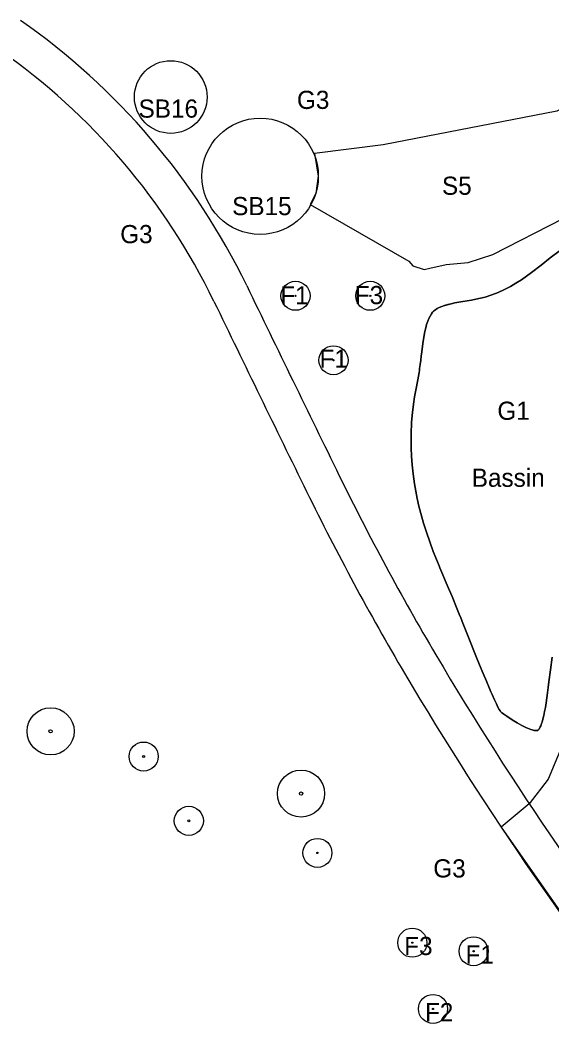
# Model space of a CAD drawing. Extents: x 0 to 512122, y 0 to 6212554.
# Drawn here: x 511664.9 to 511701.5, y 6211598.5 to 6211668.5 of the extents above; entities that cross this region are included whole.
import ezdxf

# ---------------------------------------------------------------- set-up
doc = ezdxf.new("R2010")
doc.units = 0
for name, color, linetype in [('_LØ2', 7, 'Continuous'), ('_ny fruit trees', 7, 'Continuous'), ('_Paths', 7, 'Continuous'), ('_S5_spansk kørvel', 7, 'Continuous'), ('_solitaire tree_ K3', 7, 'Continuous'), ('Bassin - bottom', 7, 'Continuous'), ('TV_U_AFM_Symbl_Gul', 7, 'Continuous'), ('TV_U_LYS_Mastenummer', 7, 'Continuous'), ('TV_U_LYS_Nyx330-Trafiksti-x2', 7, 'Continuous')]:
    doc.layers.add(name, color=color, linetype=linetype)

msp = doc.modelspace()

# ---------------------------------------------------------------- linework, layer by layer
at = {"layer": '_LØ2'}
msp.add_lwpolyline([(511711.121, 6211599.231), (511715.557, 6211615.262), (511713.457, 6211620.03), (511710.963, 6211624.728), (511708.398, 6211628.07), (511706.573, 6211631.603), (511706.496, 6211631.752), (511706.246, 6211631.811), (511705.782, 6211631.027), (511705.291, 6211628.924), (511704.763, 6211625.953), (511704.035, 6211622.995), (511702.625, 6211619.644), (511701.216, 6211616.293), (511699.914, 6211614.606), (511697.985, 6211612.99), (511704.249, 6211604.056), (511710.152, 6211596.395)], close=True, dxfattribs=at)
at = {"layer": '_ny fruit trees'}
msp.add_line((511683.868, 6211637.129), (511683.868, 6211637.129), dxfattribs=at)
for centre, radius in [((511683.843, 6211649.558), 1), ((511688.982, 6211649.558), 1), ((511683.843, 6211649.558), 0.0426), ((511688.982, 6211649.558), 0.0426), ((511686.453, 6211645.121), 1), ((511686.453, 6211645.121), 0.0426), ((511685.348, 6211611.219), 1), ((511685.348, 6211611.219), 0.0426), ((511691.873, 6211605.041), 1), ((511691.873, 6211605.041), 0.0426), ((511696.089, 6211604.454), 1), ((511696.089, 6211604.454), 0.0426), ((511693.299, 6211600.486), 1), ((511693.299, 6211600.486), 0.0426)]:
    msp.add_circle(centre, radius, dxfattribs=at)
at = {"layer": '_Paths'}
for centre, radius, start, end in [((511637.775, 6211629.597), 47.447, 25.82266, 55.10263), ((511637.775, 6211629.597), 44.947, 25.82266, 55.07394), ((514583.875, 6213055.236), 3225.465, 205.82266, 206.081191), ((514583.875, 6213055.236), 3227.965, 205.82266, 206.081191), ((511848.567, 6211716.335), 180.047, 206.08119, 210.53527), ((511848.567, 6211716.335), 182.547, 206.08119, 210.53527), ((511888.3, 6211739.773), 226.178, 210.53527, 218.4293), ((511888.3, 6211739.773), 228.678, 210.53527, 218.83127)]:
    msp.add_arc(centre, radius, start, end, dxfattribs=at)
at = {"layer": '_S5_spansk kørvel'}
msp.add_lwpolyline([(511703.238, 6211662.987), (511701.822, 6211662.264), (511689.868, 6211659.949), (511685.155, 6211659.338), (511685.411, 6211657.783), (511685.244, 6211656.619), (511684.849, 6211655.83), (511691.642, 6211651.943), (511691.91, 6211651.609), (511692.695, 6211651.377), (511693.07, 6211651.448), (511694.206, 6211651.71), (511695.721, 6211651.856), (511697.411, 6211652.409), (511702.255, 6211654.885), (511702.655, 6211656.155), (511702.821, 6211657.124), (511702.863, 6211658.926), (511702.771, 6211660.108), (511702.807, 6211661.293), (511702.978, 6211662.238)], close=True, dxfattribs=at)
msp.add_lwpolyline([(511703.238, 6211662.987), (511701.822, 6211662.264), (511689.868, 6211659.949), (511685.155, 6211659.338), (511685.411, 6211657.783), (511685.244, 6211656.619), (511684.849, 6211655.83), (511691.642, 6211651.943), (511691.91, 6211651.609), (511692.695, 6211651.377), (511693.07, 6211651.448), (511694.206, 6211651.71), (511695.721, 6211651.856), (511697.411, 6211652.409), (511702.255, 6211654.885), (511702.655, 6211656.155), (511702.821, 6211657.124), (511702.863, 6211658.926), (511702.771, 6211660.108), (511702.807, 6211661.293), (511702.978, 6211662.238)], close=True, dxfattribs=at)
at = {"layer": '_solitaire tree_ K3'}
for centre, radius in [((511667.001, 6211619.587), 1.619), ((511667.001, 6211619.587), 0.114), ((511673.398, 6211617.852), 1), ((511673.398, 6211617.852), 0.0703), ((511684.221, 6211615.306), 1.619), ((511684.221, 6211615.306), 0.114), ((511676.508, 6211613.426), 1), ((511676.508, 6211613.426), 0.0703)]:
    msp.add_circle(centre, radius, dxfattribs=at)
at = {"layer": 'Bassin - bottom'}
msp.add_lwpolyline([(511701.483, 6211624.686), (511701.366, 6211623.816), (511701.265, 6211622.996), (511701.218, 6211622.608), (511701.172, 6211622.236), (511701.125, 6211621.881), (511701.077, 6211621.546), (511701.028, 6211621.232), (511700.975, 6211620.94), (511700.92, 6211620.673), (511700.861, 6211620.432), (511700.799, 6211620.222), (511700.767, 6211620.128), (511700.735, 6211620.043), (511700.704, 6211619.966), (511700.672, 6211619.898), (511700.642, 6211619.84), (511700.614, 6211619.79), (511700.587, 6211619.749), (511700.564, 6211619.717), (511700.543, 6211619.693), (511700.527, 6211619.677), (511700.514, 6211619.665), (511700.505, 6211619.659), (511700.499, 6211619.655), (511700.494, 6211619.652), (511700.488, 6211619.65), (511700.479, 6211619.647), (511700.465, 6211619.644), (511700.444, 6211619.641), (511700.415, 6211619.639), (511700.375, 6211619.64), (511700.325, 6211619.644), (511700.264, 6211619.653), (511700.192, 6211619.668), (511700.109, 6211619.689), (511700.016, 6211619.717), (511699.913, 6211619.754), (511699.8, 6211619.799), (511699.677, 6211619.853), (511699.403, 6211619.988), (511699.094, 6211620.162), (511698.751, 6211620.375), (511698.373, 6211620.628), (511698.172, 6211620.77), (511698.068, 6211620.845), (511698.012, 6211620.886), (511698.003, 6211620.892), (511697.994, 6211620.899), (511697.988, 6211620.903), (511697.984, 6211620.906), (511697.978, 6211620.914), (511697.966, 6211620.929), (511697.947, 6211620.955), (511697.923, 6211620.991), (511697.856, 6211621.099), (511697.767, 6211621.26), (511697.655, 6211621.478), (511697.52, 6211621.76), (511697.361, 6211622.11), (511697.272, 6211622.313), (511697.176, 6211622.534), (511696.967, 6211623.029), (511696.74, 6211623.576), (511696.5, 6211624.162), (511696.254, 6211624.771), (511695.762, 6211625.999), (511695.305, 6211627.141), (511695.253, 6211627.271), (511695.201, 6211627.399), (511695.103, 6211627.644), (511694.919, 6211628.098), (511694.604, 6211628.868), (511694.35, 6211629.482), (511694.144, 6211629.971), (511693.976, 6211630.363), (511693.837, 6211630.688), (511693.774, 6211630.834), (511693.744, 6211630.904), (511693.715, 6211630.974), (511693.6, 6211631.25), (511693.316, 6211631.964), (511692.841, 6211633.298), (511692.646, 6211633.92), (511692.331, 6211635.078), (511692.208, 6211635.616), (511692.02, 6211636.614), (511691.924, 6211637.299), (511691.859, 6211637.933), (511691.82, 6211638.52), (511691.8, 6211639.063), (511691.796, 6211639.568), (511691.796, 6211639.688), (511691.797, 6211639.806), (511691.8, 6211640.035), (511691.828, 6211640.851), (511691.878, 6211641.531), (511691.945, 6211642.106), (511692.022, 6211642.609), (511692.109, 6211643.075), (511692.155, 6211643.304), (511692.201, 6211643.536), (511692.247, 6211643.775), (511692.293, 6211644.023), (511692.337, 6211644.282), (511692.358, 6211644.417), (511692.369, 6211644.486), (511692.374, 6211644.521), (511692.379, 6211644.556), (511692.416, 6211644.838), (511692.451, 6211645.125), (511692.484, 6211645.414), (511692.518, 6211645.705), (511692.591, 6211646.281), (511692.681, 6211646.837), (511692.734, 6211647.101), (511692.793, 6211647.351), (511692.86, 6211647.586), (511692.933, 6211647.801), (511693.012, 6211647.995), (511693.096, 6211648.165), (511693.184, 6211648.309), (511693.272, 6211648.427), (511693.317, 6211648.477), (511693.339, 6211648.5), (511693.35, 6211648.511), (511693.361, 6211648.521), (511693.461, 6211648.603), (511693.582, 6211648.682), (511693.727, 6211648.758), (511693.898, 6211648.829), (511694.093, 6211648.896), (511694.31, 6211648.957), (511694.025, 6211648.873), (511694.547, 6211649.013), (511694.801, 6211649.065), (511695.07, 6211649.114), (511695.351, 6211649.162), (511695.642, 6211649.211), (511695.942, 6211649.263), (511696.248, 6211649.322), (511696.56, 6211649.39), (511696.875, 6211649.47), (511697.342, 6211649.616), (511697.788, 6211649.788), (511698.213, 6211649.982), (511698.617, 6211650.195), (511699.004, 6211650.422), (511699.375, 6211650.661), (511700.074, 6211651.16), (511700.73, 6211651.67), (511701.358, 6211652.169), (511701.971, 6211652.639)], dxfattribs=at)
at = {"layer": 'TV_U_LYS_Mastenummer'}
for centre, radius in [((511675.265, 6211663.237), 2.5), ((511675.265, 6211663.237), 2.5), ((511681.411, 6211657.783), 4), ((511681.411, 6211657.783), 4)]:
    msp.add_circle(centre, radius, dxfattribs=at)
at = {"layer": 'TV_U_LYS_Nyx330-Trafiksti-x2'}
msp.add_lwpolyline([(511701.971, 6211652.639), (511701.358, 6211652.169), (511700.73, 6211651.67), (511700.074, 6211651.16), (511699.375, 6211650.661), (511699.004, 6211650.422), (511698.617, 6211650.195), (511698.213, 6211649.982), (511697.788, 6211649.788), (511697.342, 6211649.616), (511696.875, 6211649.47), (511696.56, 6211649.39), (511696.248, 6211649.322), (511695.942, 6211649.263), (511695.642, 6211649.211), (511695.351, 6211649.162), (511695.07, 6211649.114), (511694.801, 6211649.065), (511694.547, 6211649.013), (511694.31, 6211648.957), (511694.093, 6211648.896), (511693.898, 6211648.829), (511693.727, 6211648.758), (511693.582, 6211648.682), (511693.461, 6211648.603), (511693.361, 6211648.521), (511693.35, 6211648.511), (511693.339, 6211648.5), (511693.317, 6211648.477), (511693.272, 6211648.427), (511693.184, 6211648.309), (511693.096, 6211648.165), (511693.012, 6211647.995), (511692.933, 6211647.801), (511692.86, 6211647.586), (511692.793, 6211647.351), (511692.734, 6211647.101), (511692.681, 6211646.837), (511692.591, 6211646.281), (511692.518, 6211645.705), (511692.484, 6211645.414), (511692.451, 6211645.125), (511692.416, 6211644.838), (511692.379, 6211644.556), (511692.374, 6211644.521), (511692.369, 6211644.486), (511692.358, 6211644.417), (511692.337, 6211644.282), (511692.293, 6211644.023), (511692.247, 6211643.775), (511692.201, 6211643.536), (511692.155, 6211643.304), (511692.109, 6211643.075), (511692.022, 6211642.609), (511691.945, 6211642.106), (511691.878, 6211641.531), (511691.828, 6211640.851), (511691.8, 6211640.035), (511691.797, 6211639.806), (511691.796, 6211639.688), (511691.796, 6211639.568), (511691.8, 6211639.063), (511691.82, 6211638.52), (511691.859, 6211637.933), (511691.924, 6211637.299), (511692.02, 6211636.614), (511692.208, 6211635.616), (511692.331, 6211635.078), (511692.646, 6211633.92), (511692.841, 6211633.298), (511693.316, 6211631.964), (511693.6, 6211631.25), (511693.715, 6211630.974), (511693.744, 6211630.904), (511693.774, 6211630.834), (511693.837, 6211630.688), (511693.976, 6211630.363), (511694.144, 6211629.971), (511694.35, 6211629.482), (511694.604, 6211628.868), (511694.919, 6211628.098), (511695.103, 6211627.644), (511695.201, 6211627.399), (511695.253, 6211627.271), (511695.305, 6211627.141), (511695.762, 6211625.999), (511696.254, 6211624.771), (511696.5, 6211624.162), (511696.74, 6211623.576), (511696.967, 6211623.029), (511697.176, 6211622.534), (511697.272, 6211622.313), (511697.361, 6211622.11), (511697.52, 6211621.76), (511697.655, 6211621.478), (511697.767, 6211621.26), (511697.856, 6211621.099), (511697.923, 6211620.991), (511697.947, 6211620.955), (511697.966, 6211620.929), (511697.978, 6211620.914), (511697.984, 6211620.906), (511697.988, 6211620.903), (511697.994, 6211620.899), (511698.003, 6211620.892), (511698.009, 6211620.888), (511698.012, 6211620.886), (511698.013, 6211620.885), (511698.015, 6211620.883), (511698.068, 6211620.845), (511698.172, 6211620.77), (511698.373, 6211620.628), (511698.751, 6211620.375), (511699.094, 6211620.162), (511699.403, 6211619.988), (511699.677, 6211619.853), (511699.8, 6211619.799), (511699.913, 6211619.754), (511700.016, 6211619.717), (511700.109, 6211619.689), (511700.192, 6211619.668), (511700.264, 6211619.653), (511700.325, 6211619.644), (511700.375, 6211619.64), (511700.415, 6211619.639), (511700.444, 6211619.641), (511700.465, 6211619.644), (511700.479, 6211619.647), (511700.488, 6211619.65), (511700.494, 6211619.652), (511700.499, 6211619.655), (511700.505, 6211619.659), (511700.514, 6211619.665), (511700.527, 6211619.677), (511700.543, 6211619.693), (511700.564, 6211619.717), (511700.587, 6211619.749), (511700.614, 6211619.79), (511700.642, 6211619.84), (511700.672, 6211619.898), (511700.704, 6211619.966), (511700.735, 6211620.043), (511700.767, 6211620.128), (511700.799, 6211620.222), (511700.861, 6211620.432), (511700.92, 6211620.673), (511700.975, 6211620.94), (511701.028, 6211621.232), (511701.077, 6211621.546), (511701.125, 6211621.881), (511701.172, 6211622.236), (511701.218, 6211622.608), (511701.265, 6211622.996), (511701.366, 6211623.816), (511701.483, 6211624.686)], dxfattribs=at)

# ---------------------------------------------------------------- texts
at = {"layer": 'TV_U_AFM_Symbl_Gul'}
for s, p in [('SB16', (511673.05, 6211661.816)), ('G3', (511683.941, 6211662.416)), ('S5', (511693.915, 6211656.507)), ('SB15', (511679.484, 6211655.106)), ('G3', (511671.786, 6211653.177)), ('F1', (511682.795, 6211648.966)), ('F3', (511687.919, 6211648.982)), ('F1', (511685.493, 6211644.61)), ('G1', (511697.724, 6211641.023)), ('Bassin', (511695.962, 6211636.413)), ('G3', (511693.317, 6211609.531)), ('F3', (511691.319, 6211604.193)), ('F1', (511695.534, 6211603.605)), ('F2', (511692.745, 6211599.637))]:
    msp.add_text(s, height=1.25, dxfattribs=at).set_placement(p)

doc.saveas('drawing.dxf')
